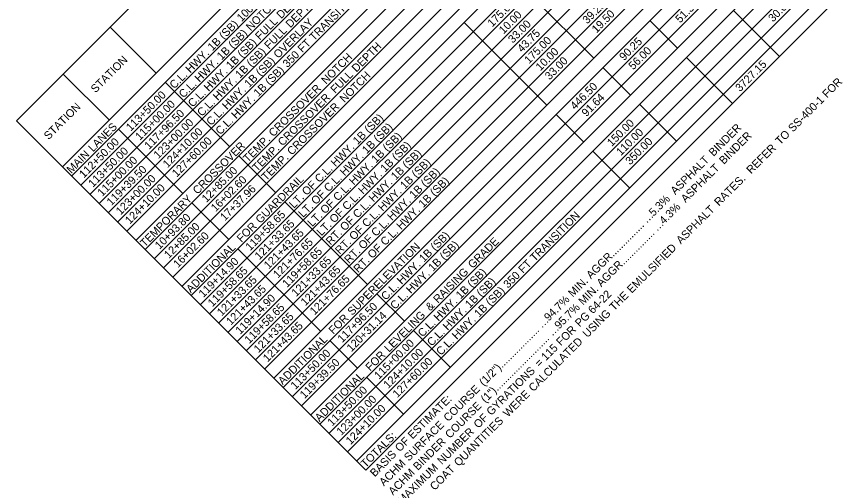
# Model space of a CAD drawing. Extents: x 1675667 to 1681231, y 227227 to 232694.
# Drawn here: x 1678525 to 1679139, y 229780 to 230133 of the extents above; entities that cross this region are included whole.
import ezdxf

# ---------------------------------------------------------------- set-up
doc = ezdxf.new("R2010")
doc.units = 0
doc.layers.add('Default', color=7, linetype='Continuous')

msp = doc.modelspace()

# ---------------------------------------------------------------- linework, layer by layer
at = {"layer": 'Default'}
for p, q in [((1678525.01, 230054.56), (1679538.35, 231068.14)), ((1678559.49, 230020.09), (1679572.82, 231033.68)), ((1678566.38, 230013.2), (1679579.72, 231026.78)), ((1678573.28, 230006.31), (1679586.61, 231019.89)), ((1678580.17, 229999.41), (1679593.51, 231013)), ((1678587.07, 229992.52), (1679600.4, 231006.1)), ((1678593.96, 229985.63), (1679607.3, 230999.21)), ((1678600.86, 229978.73), (1679614.2, 230992.32)), ((1678607.75, 229971.84), (1679621.09, 230985.42)), ((1678614.65, 229964.94), (1679627.99, 230978.53)), ((1678614.65, 229964.94), (1679627.99, 230978.53)), ((1678621.54, 229958.05), (1679634.88, 230971.64)), ((1678628.44, 229951.16), (1679641.78, 230964.74)), ((1678635.33, 229944.26), (1679648.67, 230957.85)), ((1678642.23, 229937.37), (1679655.57, 230950.96)), ((1678649.12, 229930.48), (1679662.46, 230944.06)), ((1678656.02, 229923.58), (1679669.36, 230937.17)), ((1678662.91, 229916.69), (1679676.25, 230930.28)), ((1678669.81, 229909.8), (1679683.15, 230923.38)), ((1678676.71, 229902.9), (1679690.04, 230916.49)), ((1678683.6, 229896.01), (1679696.94, 230909.6)), ((1678690.5, 229889.12), (1679703.83, 230902.7)), ((1678697.39, 229882.22), (1679710.73, 230895.81)), ((1678704.29, 229875.33), (1679717.62, 230888.92)), ((1678711.18, 229868.44), (1679724.52, 230882.02)), ((1678718.08, 229861.54), (1679731.41, 230875.13)), ((1678724.97, 229854.65), (1679738.31, 230868.24)), ((1678731.87, 229847.76), (1679745.2, 230861.34)), ((1678738.76, 229840.86), (1679752.1, 230854.45)), ((1678745.66, 229833.97), (1679758.99, 230847.55)), ((1678745.66, 229833.97), (1679758.99, 230847.55)), ((1678752.55, 229827.08), (1679765.89, 230840.66)), ((1678759.45, 229820.18), (1679772.78, 230833.77)), ((1678766.34, 229813.29), (1679779.68, 230826.87)), ((1678773.24, 229806.4), (1679786.57, 230819.98)), ((1678780.13, 229799.5), (1679793.47, 230813.09)), ((1678787.03, 229792.61), (1679800.36, 230806.19)), ((1678649.12, 229930.48), (1678959.33, 230240.76)), ((1678957.97, 230101.49), (1678895.91, 230163.54)), ((1678957.97, 230101.49), (1678895.91, 230163.54)), ((1679097.23, 230102.89), (1679062.76, 230137.36)), ((1679097.23, 230102.89), (1679062.76, 230137.36)), ((1678957.97, 230101.49), (1678993.12, 230136.66)), ((1678629.8, 230090.42), (1678595.33, 230124.89)), ((1678726.33, 229993.91), (1678860.76, 230128.37)), ((1678922.81, 230066.33), (1678860.76, 230128.37)), ((1678922.81, 230066.33), (1678860.76, 230128.37)), ((1679020.7, 230109.09), (1679000.02, 230129.77)), ((1679020.7, 230109.09), (1679000.02, 230129.77)), ((1678922.81, 230066.33), (1678957.97, 230101.49)), ((1679062.08, 230067.72), (1679027.6, 230102.19)), ((1679062.08, 230067.72), (1679027.6, 230102.19)), ((1678985.55, 230073.92), (1678964.86, 230094.6)), ((1678985.55, 230073.92), (1678964.86, 230094.6)), ((1678594.64, 230055.26), (1678560.17, 230089.72)), ((1678684.96, 230035.28), (1678636.7, 230083.53)), ((1678684.96, 230035.28), (1678636.7, 230083.53)), ((1678718.08, 229861.54), (1678922.81, 230066.33)), ((1679020.02, 230039.45), (1678992.44, 230067.03)), ((1679020.02, 230039.45), (1678992.44, 230067.03)), ((1678950.39, 230038.76), (1678929.71, 230059.44)), ((1678950.39, 230038.76), (1678929.71, 230059.44)), ((1678787.03, 229792.61), (1678525.01, 230054.56)), ((1678787.03, 229792.61), (1678525.01, 230054.56)), ((1678649.81, 230000.11), (1678601.54, 230048.36)), ((1678649.81, 230000.11), (1678601.54, 230048.36)), ((1678719.44, 230000.81), (1678691.86, 230028.38)), ((1678719.44, 230000.81), (1678691.86, 230028.38)), ((1678822.86, 229897.41), (1678957.29, 230031.86)), ((1678984.87, 230004.29), (1678957.29, 230031.86)), ((1678984.87, 230004.29), (1678957.29, 230031.86)), ((1678684.28, 229965.64), (1678656.7, 229993.22)), ((1678684.28, 229965.64), (1678656.7, 229993.22)), ((1678788.39, 229931.87), (1678726.33, 229993.91)), ((1678788.39, 229931.87), (1678726.33, 229993.91)), ((1678753.23, 229896.71), (1678691.18, 229958.75)), ((1678753.23, 229896.71), (1678691.18, 229958.75)), ((1678815.97, 229904.3), (1678795.28, 229924.98)), ((1678815.97, 229904.3), (1678795.28, 229924.98)), ((1678850.45, 229869.83), (1678822.86, 229897.41)), ((1678850.45, 229869.83), (1678822.86, 229897.41)), ((1678780.81, 229869.13), (1678760.13, 229889.82)), ((1678780.81, 229869.13), (1678760.13, 229889.82)), ((1678815.29, 229834.67), (1678787.71, 229862.24)), ((1678815.29, 229834.67), (1678787.71, 229862.24))]:
    msp.add_line(p, q, dxfattribs=at)

# ---------------------------------------------------------------- texts
for s, p in [(' DEPTH', (1678721.97, 230129.15)), (' TRANSITION', (1678746.74, 230112.55)), (' NOTCH', (1678699.14, 230120.11)), (' DEPTH', (1678728.86, 230122.25)), ('175.00', (1678881.88, 230124.57)), ('39.25', (1678953.14, 230126.89)), ('51.32', (1679022.81, 230127.63)), ('30.00', (1679092.42, 230128.31)), (' 100', (1678692.25, 230127)), ('10.00', (1678890.42, 230119.33)), ('19.50', (1678960.05, 230120.02)), (' FULL', (1678706.04, 230113.22)), (' OVERLAY', (1678719.83, 230099.43)), (' (SB)', (1678678.96, 230113.71)), ('33.00', (1678897.32, 230112.43)), (' (SB)', (1678685.86, 230106.82)), (' FULL', (1678712.93, 230106.32)), ('43.75', (1678904.19, 230105.51)), (' 1B', (1678670.38, 230105.13)), (' (SB)', (1678692.75, 230099.93)), (' FT', (1678737.97, 230103.78)), (' DEPTH', (1678778.46, 230089.12)), ('175.00', (1678909.46, 230097)), ('90.25', (1678980.72, 230099.32)), (' HWY.', (1678653.78, 230088.53)), (' 1B', (1678677.28, 230098.24)), (' (SB)', (1678699.65, 230093.03)), (' 350', (1678726.72, 230092.54)), ('10.00', (1678918, 230091.75)), ('56.00', (1678987.64, 230092.45)), ('STATION', (1678584.34, 230075.18)), (' HWY.', (1678660.68, 230081.63)), (' 1B', (1678684.18, 230091.35)), (' (SB)', (1678706.54, 230086.14)), (' NOTCH', (1678755.64, 230080.08)), ('33.00', (1678924.9, 230084.86)), ('3727.15', (1679067.71, 230076.01)), (' 1B', (1678691.07, 230084.45)), (' (SB)', (1678713.44, 230079.25)), ('C.L.', (1678643.43, 230078.17)), (' HWY.', (1678667.57, 230074.74)), (' 1B', (1678697.97, 230077.56)), (' FULL', (1678762.53, 230073.19)), (' NOTCH', (1678769.43, 230066.3)), ('C.L.', (1678650.33, 230071.28)), (' HWY.', (1678674.47, 230067.85)), (' 1B', (1678704.86, 230070.67)), (' CROSSOVER', (1678716.19, 230040.63)), ('446.50', (1678943.94, 230062.53)), (' FOR', (1679131.39, 230069.81)), ('113+50.00', (1678610.74, 230046.43)), ('C.L.', (1678657.22, 230064.39)), (' HWY.', (1678681.36, 230060.95)), ('115+00.00', (1678617.64, 230039.54)), (' HWY.', (1678688.26, 230054.06)), (' CROSSOVER', (1678723.08, 230033.73)), ('91.64', (1678952.48, 230057.29)), (' SS-400-1', (1679105.81, 230044.21)), ('STATION', (1678549.18, 230040.01)), ('117+96.50', (1678624.54, 230032.65)), ('C.L.', (1678664.12, 230057.49)), (' CROSSOVER', (1678729.98, 230026.84)), ('C.L.', (1678671.01, 230050.6)), (' (SB)', (1678787.9, 230043.4)), (' LANES', (1678580.89, 230029.41)), ('123+00.00', (1678631.43, 230025.75)), ('C.L.', (1678677.91, 230043.71)), (' (SB)', (1678794.79, 230036.51)), ('150.00', (1678971.52, 230034.96)), (' BINDER', (1679046.18, 230025.94)), ('124+10.00', (1678638.33, 230018.86)), (' 1B', (1678779.32, 230034.82)), (' (SB)', (1678801.69, 230029.61)), ('110.00', (1678978.41, 230028.06)), (' BINDER', (1679053.96, 230019.93)), (' TO', (1679096.19, 230034.6)), ('112+50.00', (1678575.59, 230011.27)), ('127+60.00', (1678645.22, 230011.97)), (' CROSSOVER', (1678659.27, 229997.48)), ('TEMP.', (1678698.59, 230023.03)), (' 1B', (1678786.21, 230027.93)), (' (SB)', (1678808.58, 230022.72)), ('350.00', (1678985.31, 230021.17)), ('MAIN', (1678566.22, 230014.74)), ('113+50.00', (1678582.48, 230004.37)), ('TEMP.', (1678705.49, 230016.13)), (' HWY.', (1678762.72, 230018.21)), (' 1B', (1678793.11, 230021.03)), (' (SB)', (1678816.46, 230016.81)), ('  REFER', (1679072.89, 230011.29)), ('115+00.00', (1678589.38, 229997.48)), ('TEMP.', (1678712.38, 230009.24)), (' HWY.', (1678769.61, 230011.32)), (' 1B', (1678800, 230014.14)), ('  ASPHALT', (1679015.99, 229995.75)), ('119+39.50', (1678596.27, 229990.59)), ('12+85.00', (1678667.55, 229992.93)), (' HWY.', (1678776.51, 230004.43)), (' 1B', (1678807.88, 230008.23)), (' (SB)', (1678823.36, 230009.92)), ('  ASPHALT', (1679023.77, 229989.74)), ('123+00.00', (1678603.17, 229983.69)), (' C.L.', (1678750.72, 230006.21)), (' HWY.', (1678783.4, 229997.53)), (' (SB)', (1678830.25, 230003.03)), ('16+02.60', (1678674.45, 229986.04)), (' GUARDRAIL', (1678706.36, 229975.64)), (' OF', (1678741.11, 229996.61)), (' C.L.', (1678757.61, 229999.32)), (' HWY.', (1678791.28, 229991.63)), (' 1B', (1678814.78, 230001.34)), (' (SB)', (1678837.15, 229996.13)), (' RATES.', (1679050.35, 229988.74)), ('124+10.00', (1678610.06, 229976.8)), ('17+37.96', (1678681.34, 229979.14)), (' OF', (1678748.01, 229989.71)), (' C.L.', (1678764.51, 229992.43)), (' HWY.', (1678798.18, 229984.73)), (' 1B', (1678821.68, 229994.45)), ('TEMPORARY', (1678621.38, 229959.59)), ('LT.', (1678733.07, 229988.56)), (' OF', (1678754.9, 229982.82)), (' C.L.', (1678771.4, 229985.53)), (' HWY.', (1678805.07, 229977.84)), (' 1B', (1678828.57, 229987.55)), ('5.3%', (1679002.85, 229982.61)), ('LT.', (1678739.96, 229981.67)), (' OF', (1678761.8, 229975.93)), (' C.L.', (1678779.29, 229979.63)), (' HWY.', (1678811.97, 229970.95)), ('4.3%', (1679010.64, 229976.6)), (' ASPHALT', (1679021.81, 229960.19)), ('10+93.80', (1678632.4, 229957.77)), ('119+58.65', (1678700.36, 229956.79)), ('LT.', (1678746.86, 229974.77)), (' OF', (1678769.68, 229970.02)), (' C.L.', (1678786.18, 229972.73)), (' TRANSITION', (1678912.22, 229947.11)), ('12+85.00', (1678639.29, 229950.88)), (' FOR', (1678692.23, 229961.5)), ('121+33.65', (1678707.25, 229949.9)), ('LT.', (1678753.75, 229967.88)), (' C.L.', (1678793.08, 229965.84)), ('…', (1678997.62, 229977.37)), ('16+02.60', (1678646.19, 229943.98)), ('121+43.65', (1678714.15, 229943.01)), ('RT.', (1678760.65, 229960.99)), (' OF', (1678776.58, 229963.12)), (' C.L.', (1678799.97, 229958.95)), (' (SB)', (1678837.55, 229955.16)), (' AGGR...............', (1678954.35, 229934.09)), ('…', (1679005.4, 229971.37)), ('121+76.65', (1678721.04, 229936.11)), ('RT.', (1678767.54, 229954.09)), (' OF', (1678783.47, 229956.23)), (' GRADE', (1678865.64, 229941.89)), (' AGGR...............', (1678962.13, 229928.08)), ('ADDITIONAL', (1678655.86, 229925.12)), ('119+58.65', (1678727.94, 229929.22)), ('RT.', (1678774.44, 229947.2)), (' SUPERELEVATION', (1678775.31, 229906.7)), (' OF', (1678790.37, 229949.34)), (' 1B', (1678828.97, 229946.58)), (' (SB)', (1678844.45, 229948.27)), (' EMULSIFIED', (1678984.91, 229923.29)), ('121+33.65', (1678734.83, 229922.33)), ('119+14.90', (1678665.23, 229921.65)), ('RT.', (1678781.33, 229940.31)), (' HWY.', (1678812.37, 229929.98)), (' 1B', (1678835.87, 229939.69)), (' FT', (1678903.45, 229938.34)), ('119+58.65', (1678672.1, 229914.74)), ('121+43.65', (1678741.73, 229915.43)), (' HWY.', (1678819.27, 229923.08)), (' RAISING', (1678839.65, 229915.9)), (' (SB)', (1678865.13, 229927.59)), (' 350', (1678892.21, 229927.09)), ('121+33.65', (1678678.99, 229907.84)), ('121+76.65', (1678748.62, 229908.54)), (' (SB)', (1678872.03, 229920.7)), (' MIN.', (1678940.71, 229920.45)), ('121+43.65', (1678685.89, 229900.95)), ('C.L.', (1678802.02, 229919.62)), (' 1B', (1678856.55, 229919.01)), (' (SB)', (1678878.92, 229913.8)), (' MIN.', (1678948.49, 229914.44)), ('119+14.90', (1678692.81, 229894.08)), ('C.L.', (1678808.92, 229912.73)), (' 1B', (1678863.45, 229912.12)), ('94.7%', (1678924.28, 229904.01)), (' 64-22', (1678955.74, 229907.9)), (' THE', (1678971.73, 229910.1)), ('119+58.65', (1678699.68, 229887.16)), ('117+96.50', (1678769.33, 229887.88)), (' &', (1678833.82, 229910.07)), (' HWY.', (1678839.95, 229902.4)), (' 1B', (1678870.34, 229905.22)), ('95.7%', (1678932.06, 229898.01)), ('121+33.65', (1678706.57, 229880.27)), ('120+31.14', (1678776.23, 229880.99)), (' LEVELING', (1678802.89, 229879.13)), (' HWY.', (1678846.85, 229895.51)), (' PG', (1678945.91, 229898.06)), (' USING', (1678951.68, 229890.05)), ('121+43.65', (1678713.47, 229873.38)), (' FOR', (1678761.18, 229892.57)), (' HWY.', (1678853.74, 229888.62)), ('…', (1678919.05, 229898.78)), ('C.L.', (1678829.6, 229892.05)), (' (1/2")..................', (1678874.01, 229853.73)), ('…', (1678926.83, 229892.77)), (' FOR', (1678931.83, 229883.98)), ('ADDITIONAL', (1678724.81, 229856.19)), ('C.L.', (1678836.5, 229885.16)), (' (1").........................', (1678875.21, 229841.14)), (' CALCULATED', (1678911.15, 229849.51)), ('115+00.00', (1678796.91, 229860.31)), ('C.L.', (1678843.39, 229878.26)), (' 115', (1678920.53, 229872.68)), ('113+50.00', (1678734.18, 229852.72)), (' FOR', (1678788.76, 229864.99)), ('124+10.00', (1678803.81, 229853.42)), ('119+39.50', (1678741.07, 229845.83)), ('127+60.00', (1678810.7, 229846.52)), (' =', (1678915.76, 229867.91)), (' GYRATIONS', (1678879.51, 229831.65)), ('ADDITIONAL', (1678752.39, 229828.61)), ('113+50.00', (1678761.76, 229825.15)), (' COURSE', (1678847.32, 229827.03)), ('123+00.00', (1678768.65, 229818.25)), (' ESTIMATE:', (1678820.52, 229814.02)), (' WERE', (1678892.04, 229830.39)), (' COURSE', (1678848.52, 229814.45)), ('124+10.00', (1678775.55, 229811.36)), (' SURFACE', (1678817.67, 229797.37)), (' QUANTITIES', (1678855.14, 229793.48)), (' OF', (1678869.9, 229822.04)), (' NUMBER', (1678842.65, 229794.78)), ('TOTALS:', (1678786.87, 229794.15)), (' OF', (1678810.92, 229804.41)), (' BINDER', (1678824.56, 229790.48)), ('BASIS', (1678793.76, 229787.25)), ('ACHM', (1678800.66, 229780.36)), ('ACHM', (1678807.55, 229773.47)), ('MAXIMUM', (1678814.45, 229766.57)), (' COAT', (1678837.14, 229775.48))]:
    msp.add_text(s, height=6, rotation=45.00703, dxfattribs=at).set_placement(p)

doc.saveas('drawing.dxf')
